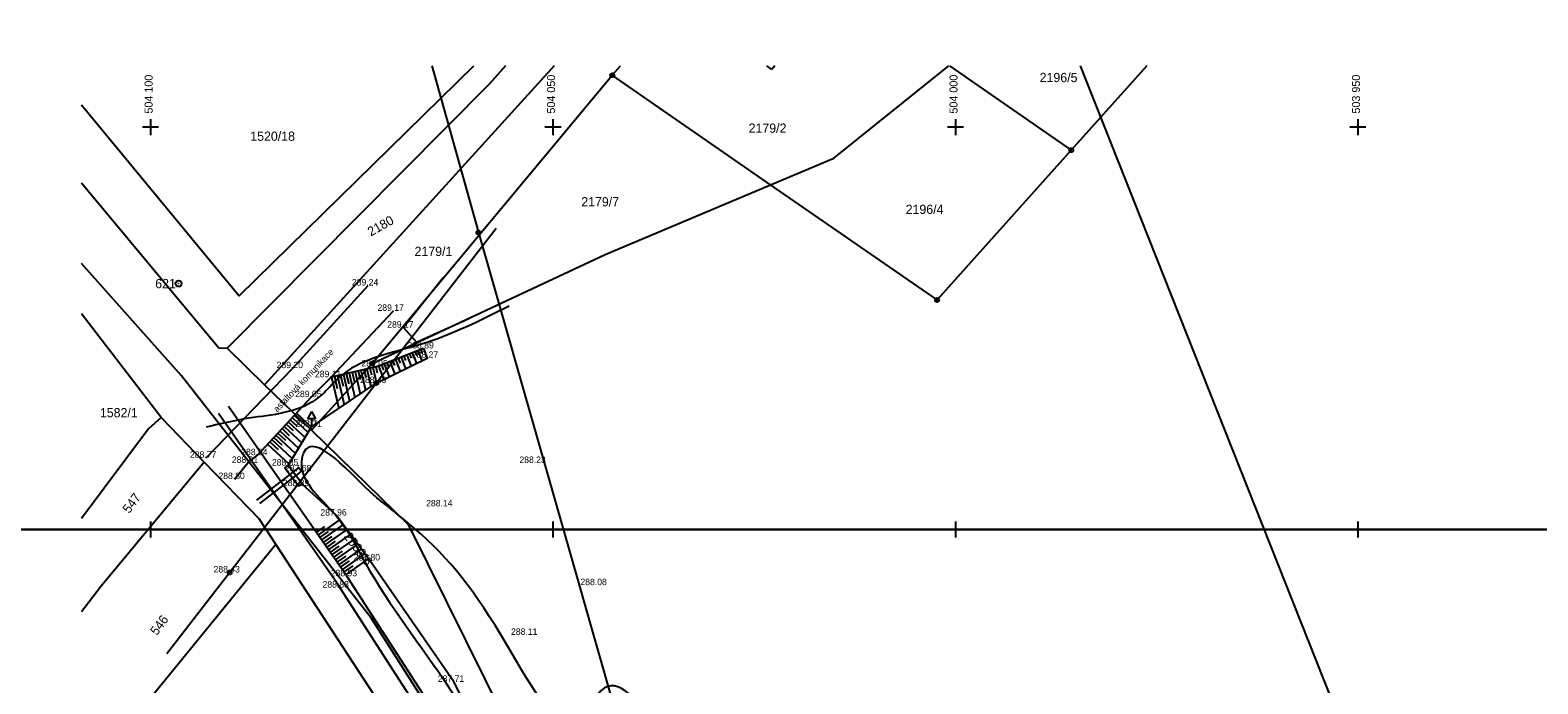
# Model space of a CAD drawing. Extents: x -504375 to -503125, y -1118000 to -1116474.
# Drawn here: x -504115 to -503927.6, y -1117519.2 to -1117437.9 of the extents above; entities that cross this region are included whole.
import ezdxf

# ---------------------------------------------------------------- set-up
doc = ezdxf.new("R2010")
doc.units = 0
for name, color, linetype in [('Druhy povrchů', 7, 'Continuous'), ('Elektro', 7, 'Continuous'), ('Kolejnice', 7, 'Continuous'), ('Komunikace', 7, 'Continuous'), ('Ostatní objekty', 7, 'Continuous'), ('Ploty', 7, 'Continuous'), ('Podkladové mapy', 7, 'Continuous'), ('Síť dekadická', 7, 'Continuous'), ('Vrstva 34', 7, 'Continuous'), ('Vrstva 48', 7, 'Continuous'), ('Výškopis', 7, 'Continuous'), ('Výšky bodů plotr', 7, 'Continuous'), ('Značky ČSN', 7, 'Continuous')]:
    doc.layers.add(name, color=color, linetype=linetype)

msp = doc.modelspace()

# ---------------------------------------------------------------- linework, layer by layer
at = {"layer": 'Elektro'}
msp.add_lwpolyline([(-504097.976, -1117515.425), (-504057.039, -1117462.536)], dxfattribs=at)
for centre in [(-504071.95, -1117481.8), (-504090.17, -1117505.34)]:
    msp.add_circle(centre, 0.25, dxfattribs=at)
at = {"layer": 'Kolejnice'}
for points in [[(-504045.958, -1117560.975), (-504047.83, -1117556.21), (-504056.76, -1117537.25), (-504065.74, -1117521.04), (-504075.61, -1117505.81), (-504090.328, -1117484.707)], [(-504047.295, -1117561.731), (-504049.25, -1117556.76), (-504058.09, -1117537.94), (-504067.12, -1117521.74), (-504076.86, -1117506.64), (-504091.539, -1117485.596)]]:
    msp.add_lwpolyline(points, dxfattribs=at)
at = {"layer": 'Komunikace'}
for p, q in [((-504079.396, -1117500.382), (-504078.325, -1117499.635)), ((-504079.181, -1117500.689), (-504076.495, -1117498.816)), ((-504078.967, -1117500.997), (-504077.889, -1117500.245)), ((-504078.752, -1117501.305), (-504076.048, -1117499.418)), ((-504078.323, -1117501.92), (-504075.601, -1117500.021)), ((-504078.538, -1117501.612), (-504077.452, -1117500.855)), ((-504078.109, -1117502.227), (-504077.016, -1117501.465)), ((-504077.894, -1117502.535), (-504075.154, -1117500.624)), ((-504077.68, -1117502.842), (-504076.58, -1117502.075)), ((-504077.465, -1117503.15), (-504074.707, -1117501.226)), ((-504077.036, -1117503.765), (-504074.26, -1117501.828)), ((-504077.251, -1117503.458), (-504076.144, -1117502.686)), ((-504076.822, -1117504.073), (-504075.707, -1117503.296)), ((-504076.607, -1117504.38), (-504073.813, -1117502.431)), ((-504076.393, -1117504.688), (-504075.271, -1117503.906)), ((-504076.178, -1117504.996), (-504073.365, -1117503.034)), ((-504075.749, -1117505.611), (-504072.918, -1117503.636)), ((-504075.964, -1117505.303), (-504074.835, -1117504.516))]:
    msp.add_line(p, q, dxfattribs=at)
for points in [[(-504093.1, -1117491.09), (-504082.33, -1117479.95), (-504072.98, -1117469.68)], [(-504089.56, -1117493.73), (-504087.9, -1117491.72), (-504086.73, -1117490.76), (-504080.03, -1117483.55), (-504077.57, -1117481.08), (-504069.8, -1117472.83)], [(-504076.9, -1117498.27), (-504081.21, -1117494.34)], [(-504072.76, -1117503.85), (-504076.9, -1117498.27)], [(-504062.31, -1117518.93), (-504072.76, -1117503.85)], [(-504053.77, -1117535.85), (-504062.31, -1117518.93)]]:
    msp.add_lwpolyline(points, dxfattribs=at)
at = {"layer": 'Ostatní objekty'}
for points in [[(-504082.301, -1117492.853), (-504086.816, -1117496.334)], [(-504081.57, -1117492.29), (-504082.301, -1117492.853)], [(-504081.57, -1117492.29), (-504081.229, -1117492.733), (-504081.959, -1117493.296)], [(-504081.959, -1117493.296), (-504086.474, -1117496.777)]]:
    msp.add_lwpolyline(points, dxfattribs=at)
msp.add_lwpolyline([(-504081.56, -1117494.61), (-504081.175, -1117494.313), (-504082.92, -1117492.05), (-504083.305, -1117492.347)], close=True, dxfattribs=at)
at = {"layer": 'Ploty'}
msp.add_lwpolyline([(-504063.632, -1117468.74), (-504068.59, -1117474.91), (-504066.94, -1117476.7), (-504060.47, -1117473.774)], dxfattribs=at)
at = {"layer": 'Podkladové mapy'}
for p, q in [((-504089, -1117470.98), (-504059.83, -1117442.374)), ((-504049.833, -1117442.374), (-504085.83, -1117482.01)), ((-504065.069, -1117442.374), (-504059.26, -1117463.1)), ((-504055.919, -1117442.374), (-504057.87, -1117444.6)), ((-504042.64, -1117443.55), (-504041.599, -1117442.374)), ((-504022.83, -1117442.84), (-504023.426, -1117442.374)), ((-504022.421, -1117442.374), (-504022.83, -1117442.84)), ((-504015.12, -1117453.86), (-504000.82, -1117442.374)), ((-504000.755, -1117442.374), (-503985.61, -1117452.86)), ((-503976.214, -1117442.374), (-503985.61, -1117452.86)), ((-503984.514, -1117442.374), (-503935.19, -1117566.81)), ((-504072.45, -1117479.38), (-504042.64, -1117443.55)), ((-504022.97, -1117457.16), (-504042.64, -1117443.55)), ((-504057.87, -1117444.6), (-504090.49, -1117477.48)), ((-504108.579, -1117447.226), (-504089, -1117470.98)), ((-503985.61, -1117452.86), (-504002.29, -1117471.48)), ((-504022.97, -1117457.16), (-504015.12, -1117453.86)), ((-504108.578, -1117456.906), (-504091.5, -1117477.43)), ((-504043.52, -1117465.81), (-504022.97, -1117457.16)), ((-504002.29, -1117471.48), (-504022.97, -1117457.16)), ((-504059.51, -1117463.05), (-504059.46, -1117462.95)), ((-504059.46, -1117462.95), (-504059.41, -1117462.9)), ((-504059.41, -1117462.9), (-504059.31, -1117462.85)), ((-504059.31, -1117462.85), (-504059.21, -1117462.85)), ((-504059.31, -1117463.25), (-504059.31, -1117462.95)), ((-504059.31, -1117462.95), (-504059.21, -1117462.95)), ((-504059.21, -1117462.85), (-504059.11, -1117462.9)), ((-504059.21, -1117462.95), (-504059.21, -1117463.25)), ((-504059.11, -1117462.9), (-504059.06, -1117462.95)), ((-504059.06, -1117462.95), (-504059.01, -1117463.05)), ((-504059.51, -1117463.15), (-504059.51, -1117463.05)), ((-504059.46, -1117463.25), (-504059.51, -1117463.15)), ((-504059.41, -1117463.3), (-504059.46, -1117463.25)), ((-504059.41, -1117463), (-504059.41, -1117463.2)), ((-504059.41, -1117463.2), (-504059.31, -1117463.25)), ((-504059.31, -1117463.35), (-504059.41, -1117463.3)), ((-504059.21, -1117463.35), (-504059.31, -1117463.35)), ((-504059.26, -1117463.1), (-504028.19, -1117571.77)), ((-504059.21, -1117463.25), (-504059.11, -1117463.2)), ((-504059.11, -1117463.3), (-504059.21, -1117463.35)), ((-504059.11, -1117463.2), (-504059.11, -1117463)), ((-504059.06, -1117463.25), (-504059.11, -1117463.3)), ((-504059.01, -1117463.15), (-504059.06, -1117463.25)), ((-504059.01, -1117463.05), (-504059.01, -1117463.15)), ((-504072.45, -1117479.38), (-504043.52, -1117465.81)), ((-504096.17, -1117480.9), (-504108.577, -1117466.948)), ((-504098.69, -1117486.09), (-504108.576, -1117473.195)), ((-504091.5, -1117477.43), (-504090.49, -1117477.48)), ((-504090.49, -1117477.48), (-504085.83, -1117482.01)), ((-504080, -1117487.67), (-504072.45, -1117479.38)), ((-504072.54, -1117511.04), (-504096.17, -1117480.9)), ((-504085.83, -1117482.01), (-504080, -1117487.67)), ((-504098.69, -1117486.09), (-504100.26, -1117487.5)), ((-504098.69, -1117486.09), (-504093.33, -1117491.63)), ((-504100.26, -1117487.5), (-504108.574, -1117498.62)), ((-504080, -1117487.67), (-504067.98, -1117499.36)), ((-504093.33, -1117491.63), (-504106.12, -1117507.04)), ((-504093.33, -1117491.63), (-504086.54, -1117498.64)), ((-504086.54, -1117498.64), (-504084.44, -1117501.87)), ((-504067.98, -1117499.36), (-504050.14, -1117535.4)), ((-504084.44, -1117501.87), (-504102.21, -1117523.64)), ((-504084.44, -1117501.87), (-504065.39, -1117531.05)), ((-504106.12, -1117507.04), (-504108.573, -1117510.236)), ((-504064.67, -1117523.45), (-504072.54, -1117511.04))]:
    msp.add_line(p, q, dxfattribs=at)
for centre, radius in [((-504042.64, -1117443.55), 0.25), ((-504042.64, -1117443.55), 0.005), ((-503985.61, -1117452.86), 0.25), ((-503985.61, -1117452.86), 0.005), ((-504096.52, -1117469.44), 0.375), ((-504096.52, -1117469.44), 0.005), ((-504002.29, -1117471.48), 0.25), ((-504002.29, -1117471.48), 0.005), ((-504072.45, -1117479.38), 0.25), ((-504072.45, -1117479.38), 0.005)]:
    msp.add_circle(centre, radius, dxfattribs=at)
at = {"layer": 'Síť dekadická'}
for points in [[(-503750, -1117000), (-503750, -1117500), (-504375, -1117500), (-504375, -1117000)], [(-503750, -1117500), (-503750, -1118000), (-504375, -1118000), (-504375, -1117500)]]:
    msp.add_lwpolyline(points, close=True, dxfattribs=at)
at = {"layer": 'Vrstva 34'}
for p, q in [((-504100, -1117449), (-504100, -1117451)), ((-504050, -1117449), (-504050, -1117451)), ((-504000, -1117449), (-504000, -1117451)), ((-503950, -1117449), (-503950, -1117451)), ((-504099, -1117450), (-504101, -1117450)), ((-504049, -1117450), (-504051, -1117450)), ((-503999, -1117450), (-504001, -1117450)), ((-503949, -1117450), (-503951, -1117450)), ((-504099, -1117500), (-504101, -1117500)), ((-504100, -1117499), (-504100, -1117501)), ((-504049, -1117500), (-504051, -1117500)), ((-504050, -1117499), (-504050, -1117501)), ((-503999, -1117500), (-504001, -1117500)), ((-504000, -1117499), (-504000, -1117501)), ((-503949, -1117500), (-503951, -1117500)), ((-503950, -1117499), (-503950, -1117501))]:
    msp.add_line(p, q, dxfattribs=at)
msp.add_lwpolyline([(-503831.557, -1117500), (-504108.579, -1117500)], dxfattribs=at)
at = {"layer": 'Vrstva 48'}
for points in [[(-504055.459, -1117472.257), (-504066.501, -1117477.021), (-504076.631, -1117481.165), (-504078.201, -1117482.775), (-504079.942, -1117484.161), (-504088.31, -1117486.257), (-504093.082, -1117487.296)], [(-504071.865, -1117496.063), (-504072.24, -1117495.739), (-504080.975, -1117490.459), (-504081.197, -1117491.163), (-504077.039, -1117498.176), (-504073.296, -1117504.18), (-504062.968, -1117519.552), (-504045.254, -1117555.159), (-504038.611, -1117571.573), (-504034.463, -1117582.612)], [(-504030.547, -1117581.497), (-504033.275, -1117570.177), (-504036.945, -1117549.405), (-504033.445, -1117534.587), (-504036.56, -1117525.353), (-504043.634, -1117519.705), (-504046.562, -1117523.689), (-504055.611, -1117514.52), (-504067.206, -1117499.872), (-504071.866, -1117496.062)]]:
    msp.add_spline(points, degree=3, dxfattribs=at)
at = {"layer": 'Výškopis'}
for p, q in [((-504067.128, -1117477.91), (-504066.927, -1117478.423)), ((-504066.778, -1117477.773), (-504066.288, -1117479.026)), ((-504066.429, -1117477.637), (-504066.237, -1117478.126)), ((-504066.08, -1117477.5), (-504065.612, -1117478.695)), ((-504072.026, -1117479.792), (-504071.856, -1117480.527)), ((-504071.667, -1117479.688), (-504071.019, -1117481.344)), ((-504071.318, -1117479.551), (-504071.063, -1117480.202)), ((-504070.969, -1117479.414), (-504070.343, -1117481.013)), ((-504070.619, -1117479.278), (-504070.373, -1117479.905)), ((-504070.27, -1117479.141), (-504069.667, -1117480.682)), ((-504069.921, -1117479.004), (-504069.684, -1117479.609)), ((-504069.572, -1117478.867), (-504068.991, -1117480.351)), ((-504069.223, -1117478.731), (-504068.995, -1117479.312)), ((-504068.873, -1117478.594), (-504068.315, -1117480.019)), ((-504068.524, -1117478.457), (-504068.305, -1117479.016)), ((-504068.175, -1117478.32), (-504067.639, -1117479.688)), ((-504067.826, -1117478.184), (-504067.616, -1117478.719)), ((-504067.477, -1117478.047), (-504066.964, -1117479.357)), ((-504077.505, -1117481.065), (-504076.602, -1117484.954)), ((-504077.14, -1117480.98), (-504076.792, -1117482.479)), ((-504076.775, -1117480.895), (-504075.937, -1117484.503)), ((-504076.409, -1117480.81), (-504076.087, -1117482.197)), ((-504076.044, -1117480.726), (-504075.272, -1117484.052)), ((-504075.679, -1117480.641), (-504075.383, -1117481.915)), ((-504075.314, -1117480.556), (-504074.606, -1117483.601)), ((-504074.948, -1117480.471), (-504074.679, -1117481.633)), ((-504074.583, -1117480.386), (-504073.941, -1117483.15)), ((-504074.218, -1117480.301), (-504073.974, -1117481.351)), ((-504073.852, -1117480.217), (-504073.276, -1117482.699)), ((-504073.487, -1117480.132), (-504073.27, -1117481.069)), ((-504073.122, -1117480.047), (-504072.61, -1117482.248)), ((-504072.757, -1117479.962), (-504072.565, -1117480.786)), ((-504072.391, -1117479.877), (-504071.946, -1117481.798)), ((-504083.408, -1117487.185), (-504081.202, -1117489.235)), ((-504083.153, -1117486.911), (-504082.293, -1117487.71)), ((-504082.898, -1117486.636), (-504080.803, -1117488.582)), ((-504082.642, -1117486.361), (-504081.827, -1117487.119)), ((-504082.387, -1117486.087), (-504080.404, -1117487.929)), ((-504082.132, -1117485.812), (-504081.361, -1117486.528)), ((-504081.877, -1117485.537), (-504080.006, -1117487.276)), ((-504085.195, -1117489.108), (-504084.156, -1117490.074)), ((-504084.94, -1117488.834), (-504082.398, -1117491.195)), ((-504084.685, -1117488.559), (-504083.69, -1117489.483)), ((-504084.429, -1117488.284), (-504081.999, -1117490.542)), ((-504084.174, -1117488.01), (-504083.225, -1117488.892)), ((-504083.919, -1117487.735), (-504081.601, -1117489.889)), ((-504083.664, -1117487.46), (-504082.759, -1117488.301)), ((-504085.45, -1117489.383), (-504082.797, -1117491.849))]:
    msp.add_line(p, q, dxfattribs=at)
for points in [[(-504066.08, -1117477.5), (-504071.8, -1117479.74), (-504077.57, -1117481.08)], [(-504079.99, -1117487.25), (-504071.95, -1117481.8), (-504065.54, -1117478.66)], [(-504082.92, -1117492.05), (-504079.99, -1117487.25)]]:
    msp.add_lwpolyline(points, dxfattribs=at)
at = {"layer": 'Značky ČSN'}
for p, q in [((-504079.99, -1117485.35), (-504080.49, -1117486.25)), ((-504079.99, -1117485.35), (-504079.49, -1117486.25)), ((-504079.49, -1117486.25), (-504080.49, -1117486.25)), ((-504079.99, -1117486.25), (-504079.99, -1117487.25))]:
    msp.add_line(p, q, dxfattribs=at)

# ---------------------------------------------------------------- texts
at = {"layer": 'Druhy povrchů'}
msp.add_text('asfaltová komunikace', height=0.8, rotation=46.59022, dxfattribs=at).set_placement((-504084.247, -1117485.473))
at = {"layer": 'Podkladové mapy'}
for s, p in [('2196/5', (-503989.54, -1117444.41)), ('2179/2', (-504025.7, -1117450.7)), ('1520/18', (-504087.612, -1117451.699)), ('2179/7', (-504046.491, -1117459.85)), ('2196/4', (-504006.19, -1117460.79)), ('2179/1', (-504067.203, -1117466.012)), ('621', (-504099.416, -1117470.015)), ('1582/1', (-504106.289, -1117486.059))]:
    msp.add_text(s, height=1.15, dxfattribs=at).set_placement(p)
for s, rotation, p in [('2180', 29.4354, (-504072.63, -1117463.601)), ('547', 53.66709, (-504102.65, -1117498.086)), ('2563/6', 307.24749, (-504076.07, -1117500.88)), ('546', 53.70741, (-504099.216, -1117513.244))]:
    msp.add_text(s, height=1.15, rotation=rotation, dxfattribs=at).set_placement(p)
at = {"layer": 'Vrstva 34'}
for s, p in [('504 100', (-504099.738, -1117448.315)), ('504 050', (-504049.738, -1117448.315)), ('504 000', (-503999.738, -1117448.315)), ('503 950', (-503949.738, -1117448.315))]:
    msp.add_text(s, height=1, rotation=90, dxfattribs=at).set_placement(p)
at = {"layer": 'Výšky bodů plotr'}
for s, p in [('289.24 ', (-504074.98, -1117469.68)), ('289.17 ', (-504071.8, -1117472.83)), ('289.17 ', (-504070.59, -1117474.91)), ('288.89 ', (-504068.08, -1117477.5)), ('288.27 ', (-504067.54, -1117478.66)), ('289.20 ', (-504084.33, -1117479.95)), ('289.05 ', (-504073.8, -1117479.74)), ('289.11 ', (-504079.57, -1117481.08)), ('288.49 ', (-504073.95, -1117481.8)), ('289.05 ', (-504082.03, -1117483.55)), ('288.71 ', (-504081.99, -1117487.25)), ('288.77 ', (-504095.1, -1117491.09)), ('288.91 ', (-504089.9, -1117491.72)), ('288.94 ', (-504088.73, -1117490.76)), ('288.23 ', (-504054.17, -1117491.73)), ('288.80 ', (-504091.56, -1117493.73)), ('288.85 ', (-504084.92, -1117492.05)), ('287.68 ', (-504083.29, -1117492.78)), ('288.89 ', (-504083.56, -1117494.61)), ('288.14 ', (-504065.76, -1117497.12)), ('287.96 ', (-504078.9, -1117498.27)), ('287.80 ', (-504074.76, -1117503.85)), ('288.43 ', (-504092.17, -1117505.34)), ('288.93 ', (-504077.61, -1117505.81)), ('288.88 ', (-504078.626, -1117507.214)), ('288.08 ', (-504046.59, -1117506.91)), ('288.11 ', (-504055.21, -1117513.09)), ('287.71 ', (-504064.31, -1117518.93))]:
    msp.add_text(s, height=0.8, dxfattribs=at).set_placement(p)

doc.saveas('drawing.dxf')
